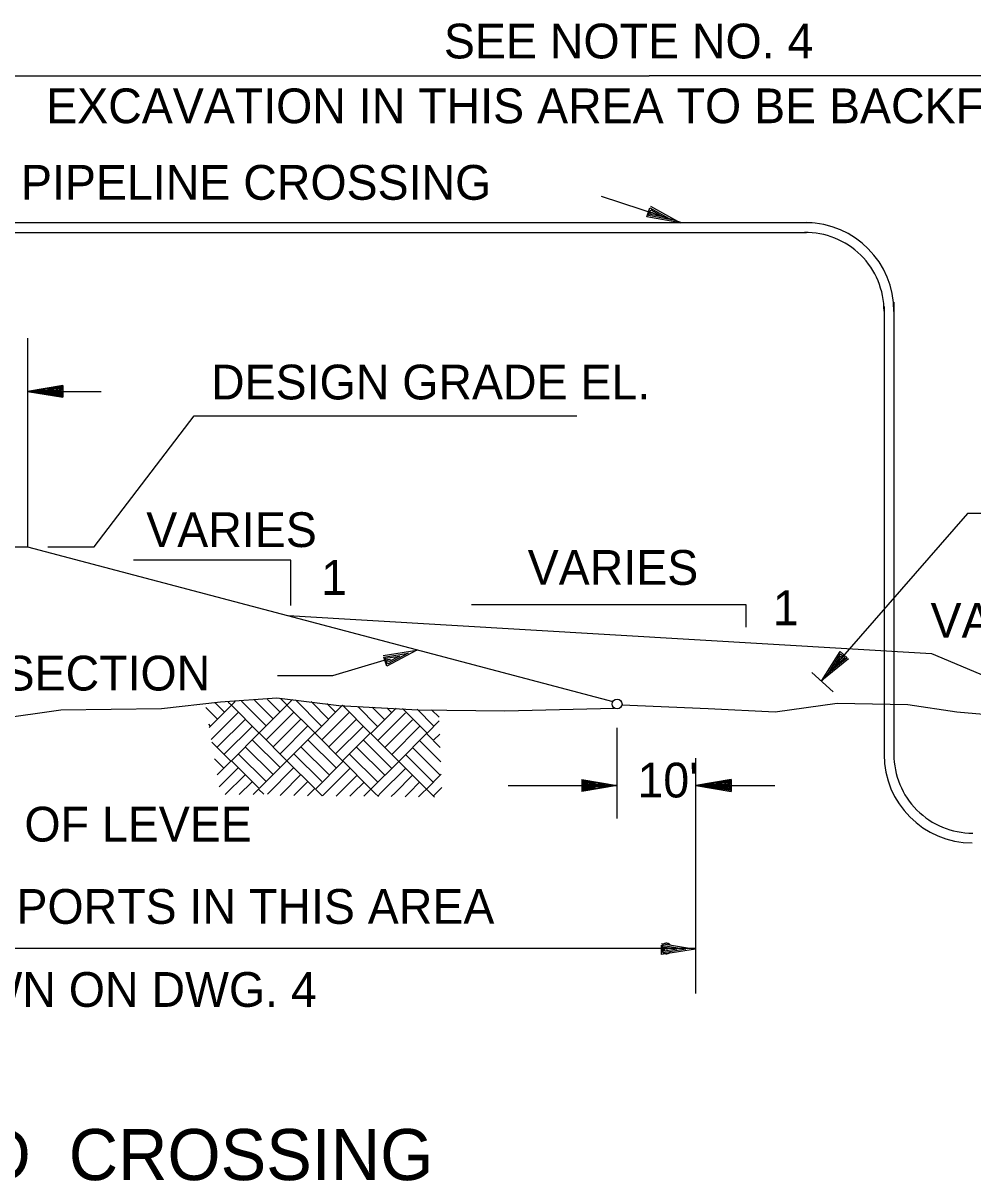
# Model space of a CAD drawing. Extents: x 2127959 to 2137375, y 2146193 to 2153470.
# Drawn here: x 2131195 to 2132094, y 2151641 to 2152738 of the extents above; entities that cross this region are included whole.
import ezdxf

# ---------------------------------------------------------------- set-up
doc = ezdxf.new("R2010")
doc.units = 0
for name, color, linetype in [('Level 1', 7, 'Continuous'), ('Level 3', 7, 'Continuous'), ('Level 5', 7, 'Continuous'), ('Level 50', 7, 'Continuous'), ('Level 63', 7, 'Continuous')]:
    doc.layers.add(name, color=color, linetype=linetype)

msp = doc.modelspace()

# ---------------------------------------------------------------- linework, layer by layer
at = {"layer": 'Level 1'}
for p, q in [((2131262.215, 2152241.498), (2131356.906, 2152365.575)), ((2132089.203, 2152273.049), (2131951.407, 2152114.92)), ((2132154.777, 2152273.049), (2132089.203, 2152273.049)), ((2131124.455, 2152241.498), (2131198.918, 2152241.498)), ((2131124.455, 2152241.498), (2131198.918, 2152241.498)), ((2131124.455, 2152241.498), (2131198.918, 2152241.498)), ((2131198.918, 2152241.498), (2131445.274, 2152176.493)), ((2131198.918, 2152241.498), (2131445.274, 2152176.493)), ((2131198.918, 2152241.498), (2131445.274, 2152176.493)), ((2131218.289, 2152241.498), (2131262.215, 2152241.498)), ((2131448.487, 2152228.906), (2131299.456, 2152228.906)), ((2131448.487, 2152185.957), (2131448.487, 2152228.906)), ((2131445.274, 2152176.493), (2131753.511, 2152095.134)), ((2131445.796, 2152176.343), (2132055.253, 2152140.601)), ((2131445.796, 2152176.343), (2132055.253, 2152140.601)), ((2131445.796, 2152176.343), (2132055.253, 2152140.601)), ((2132055.253, 2152140.601), (2132204.181, 2152077.145)), ((2132055.253, 2152140.601), (2132204.181, 2152077.145)), ((2132055.253, 2152140.601), (2132204.181, 2152077.145)), ((2131536.435, 2152133.706), (2131487.73, 2152119.307)), ((2131487.73, 2152119.307), (2131435.705, 2152119.307))]:
    msp.add_line(p, q, dxfattribs=at)
at = {"layer": 'Level 3'}
for p, q in [((2131161.687, 2152687.675), (2131787.674, 2152687.675)), ((2132413.663, 2152687.675), (2131787.674, 2152687.675)), ((2130351.811, 2152548.663), (2131942.143, 2152548.663)), ((2130351.811, 2152548.663), (2131942.143, 2152548.663)), ((2130351.811, 2152548.663), (2131942.143, 2152548.663)), ((2130352.15, 2152539.354), (2131936.796, 2152539.354)), ((2130352.15, 2152539.354), (2131936.796, 2152539.354)), ((2130352.15, 2152539.354), (2131936.796, 2152539.354)), ((2132010.232, 2152469.36), (2132010.232, 2152044.692)), ((2132010.232, 2152469.36), (2132010.232, 2152044.692)), ((2132010.232, 2152469.36), (2132010.232, 2152044.692)), ((2132019.54, 2152473.381), (2132019.54, 2152044.841)), ((2132019.54, 2152473.381), (2132019.54, 2152044.841)), ((2132019.54, 2152473.381), (2132019.54, 2152044.841)), ((2131198.918, 2152439.126), (2131198.918, 2152241.498)), ((2131232.383, 2152394.404), (2131198.918, 2152388.834)), ((2131231.698, 2152393.734), (2131204.563, 2152389.223)), ((2131231.116, 2152393.034), (2131209.955, 2152389.638)), ((2131230.312, 2152392.215), (2131217.953, 2152390.353)), ((2131229.745, 2152391.56), (2131226.202, 2152391.024)), ((2131229.687, 2152390.544), (2131229.745, 2152391.56)), ((2131230.373, 2152390.174), (2131230.312, 2152392.215)), ((2131231.163, 2152389.533), (2131231.116, 2152393.034)), ((2131231.742, 2152389.624), (2131231.698, 2152393.734)), ((2131232.383, 2152394.404), (2131232.383, 2152383.248)), ((2131198.918, 2152388.834), (2131268.706, 2152388.834)), ((2131198.918, 2152388.834), (2131268.706, 2152388.834)), ((2131198.918, 2152388.834), (2131268.706, 2152388.834)), ((2131198.918, 2152388.834), (2131232.383, 2152388.834)), ((2131198.918, 2152388.834), (2131232.383, 2152383.248)), ((2131204.563, 2152389.223), (2131231.163, 2152389.533)), ((2131231.848, 2152384.01), (2131204.653, 2152388.314)), ((2131204.653, 2152388.314), (2131231.116, 2152388.314)), ((2131209.955, 2152389.638), (2131230.373, 2152390.174)), ((2131231.191, 2152384.679), (2131210.09, 2152387.894)), ((2131210.09, 2152387.894), (2131230.444, 2152387.687)), ((2131217.953, 2152390.353), (2131229.687, 2152390.544)), ((2131230.434, 2152385.47), (2131218.116, 2152387.241)), ((2131218.116, 2152387.241), (2131229.776, 2152387.048)), ((2131229.927, 2152386.079), (2131226.188, 2152386.571)), ((2131229.776, 2152387.048), (2131229.927, 2152386.079)), ((2131230.444, 2152387.687), (2131230.434, 2152385.47)), ((2131231.116, 2152388.314), (2131231.191, 2152384.679)), ((2131231.786, 2152388.284), (2131231.848, 2152384.01)), ((2131356.906, 2152365.575), (2131719.112, 2152365.575)), ((2131619.625, 2152186.904), (2131879.397, 2152186.904)), ((2131879.397, 2152186.904), (2131879.397, 2152165.564)), ((2131941.981, 2152122.533), (2131961.923, 2152104.287)), ((2131757.396, 2151984.244), (2131757.396, 2152069.964)), ((2131757.396, 2151984.244), (2131757.396, 2152069.964)), ((2131757.396, 2151984.244), (2131757.396, 2152069.964)), ((2131831.86, 2151818.472), (2131831.86, 2152041.223)), ((2131831.86, 2151818.472), (2131831.86, 2152041.223)), ((2131831.86, 2151818.472), (2131831.86, 2152041.223)), ((2131723.916, 2152021.043), (2131723.916, 2152009.873)), ((2131723.916, 2152021.043), (2131757.396, 2152015.457)), ((2131724.573, 2152020.059), (2131724.527, 2152015.935)), ((2131725.288, 2152020.118), (2131725.272, 2152016.442)), ((2131752.437, 2152015.818), (2131725.288, 2152020.118)), ((2131746.182, 2152016.291), (2131726.019, 2152019.287)), ((2131726.019, 2152019.287), (2131726.019, 2152017.231)), ((2131736.8, 2152017.053), (2131726.808, 2152018.646)), ((2131726.808, 2152018.646), (2131726.836, 2152017.811)), ((2131865.324, 2152021.043), (2131831.86, 2152015.457)), ((2131864.64, 2152020.36), (2131837.505, 2152015.847)), ((2131864.06, 2152019.658), (2131842.897, 2152016.263)), ((2131863.254, 2152018.838), (2131850.894, 2152016.978)), ((2131863.313, 2152016.815), (2131863.254, 2152018.838)), ((2131864.105, 2152016.157), (2131864.06, 2152019.658)), ((2131864.684, 2152016.247), (2131864.64, 2152020.36)), ((2131865.324, 2152021.043), (2131865.324, 2152009.873)), ((2131654.102, 2152015.457), (2131757.396, 2152015.457)), ((2131654.102, 2152015.457), (2131757.396, 2152015.457)), ((2131654.102, 2152015.457), (2131757.396, 2152015.457)), ((2131757.396, 2152015.457), (2131723.916, 2152015.457)), ((2131757.396, 2152015.457), (2131723.916, 2152009.873)), ((2131724.396, 2152010.56), (2131752.394, 2152015.042)), ((2131724.544, 2152014.905), (2131724.396, 2152010.56)), ((2131724.527, 2152015.935), (2131752.437, 2152015.818)), ((2131752.394, 2152015.042), (2131725.229, 2152014.923)), ((2131725.229, 2152014.923), (2131725.229, 2152011.35)), ((2131725.229, 2152011.35), (2131745.988, 2152014.461)), ((2131725.272, 2152016.442), (2131746.182, 2152016.291)), ((2131745.988, 2152014.461), (2131725.929, 2152014.178)), ((2131725.929, 2152014.178), (2131726.001, 2152012.105)), ((2131726.001, 2152012.105), (2131736.949, 2152013.581)), ((2131726.019, 2152017.231), (2131736.8, 2152017.053)), ((2131736.949, 2152013.581), (2131726.778, 2152013.639)), ((2131726.778, 2152013.639), (2131726.79, 2152012.808)), ((2131726.79, 2152012.808), (2131729.89, 2152013.063)), ((2131726.836, 2152017.811), (2131730.01, 2152017.721)), ((2131831.86, 2152015.457), (2131906.682, 2152015.457)), ((2131831.86, 2152015.457), (2131865.324, 2152015.457)), ((2131831.86, 2152015.457), (2131865.324, 2152009.873)), ((2131837.505, 2152015.847), (2131864.105, 2152016.157)), ((2131864.789, 2152010.635), (2131837.595, 2152014.937)), ((2131837.595, 2152014.937), (2131864.06, 2152014.937)), ((2131842.897, 2152016.263), (2131863.313, 2152016.815)), ((2131864.134, 2152011.32), (2131843.031, 2152014.522)), ((2131843.031, 2152014.522), (2131863.387, 2152014.312)), ((2131850.894, 2152016.978), (2131862.631, 2152017.185)), ((2131863.377, 2152012.094), (2131851.059, 2152013.879)), ((2131851.059, 2152013.879), (2131862.718, 2152013.686)), ((2131862.869, 2152012.701), (2131859.129, 2152013.194)), ((2131862.687, 2152018.198), (2131859.145, 2152017.66)), ((2131862.631, 2152017.185), (2131862.687, 2152018.198)), ((2131862.718, 2152013.686), (2131862.869, 2152012.701)), ((2131863.387, 2152014.312), (2131863.377, 2152012.094)), ((2131864.06, 2152014.937), (2131864.134, 2152011.32)), ((2131864.728, 2152014.923), (2131864.789, 2152010.635)), ((2131831.86, 2151861.007), (2131143.071, 2151861.007)), ((2131831.86, 2151861.007), (2131143.071, 2151861.007)), ((2131831.86, 2151861.007), (2131143.071, 2151861.007))]:
    msp.add_line(p, q, dxfattribs=at)
msp.add_lwpolyline([(2131817.726, 2152548.663), (2131742.598, 2152573.44)], dxfattribs=at)
msp.add_circle((2131757.397, 2152092.572), 4.646, dxfattribs=at)
msp.add_circle((2131757.397, 2152092.572), 4.646, dxfattribs=at)
msp.add_circle((2131757.397, 2152092.572), 4.646, dxfattribs=at)
for centre, radius, start, end in [((2131935.764, 2152464.89), 83.775, 359.817047, 89.549108), ((2131935.764, 2152464.89), 83.775, 359.817047, 89.549108), ((2131935.764, 2152464.89), 83.775, 359.817047, 89.549108), ((2131935.755, 2152464.886), 74.476, 359.901381, 90.780836), ((2131935.755, 2152464.886), 74.476, 359.901381, 90.780836), ((2131935.755, 2152464.886), 74.476, 359.901381, 90.780836), ((2132094.001, 2152044.781), 83.771, 179.948172, 269.787253), ((2132094.001, 2152044.781), 83.771, 179.948172, 269.787253), ((2132094.001, 2152044.781), 83.771, 179.948172, 269.787253), ((2132094.001, 2152044.781), 74.463, 179.792758, 270.162028), ((2132094.001, 2152044.781), 74.463, 179.792758, 270.162028), ((2132094.001, 2152044.781), 74.463, 179.792758, 270.162028)]:
    msp.add_arc(centre, radius, start, end, dxfattribs=at)
at = {"layer": 'Level 5'}
for p, q in [((2131381.788, 2152094.731), (2131435.265, 2152098.574)), ((2131381.788, 2152094.731), (2131435.265, 2152098.574)), ((2131381.788, 2152094.731), (2131435.265, 2152098.574)), ((2131431.605, 2152078.44), (2131413.881, 2152096.161)), ((2131426.274, 2152096.965), (2131438.199, 2152085.023)), ((2131435.265, 2152098.574), (2131493.841, 2152091.129)), ((2131435.265, 2152098.574), (2131493.841, 2152091.129)), ((2131435.265, 2152098.574), (2131493.841, 2152091.129)), ((2131438.586, 2152097.769), (2131444.873, 2152091.485)), ((2131444.752, 2152091.591), (2131450.012, 2152096.845)), ((2131477.549, 2152071.722), (2131452.706, 2152096.551)), ((2131151.991, 2152075.983), (2131230.701, 2152087.046)), ((2131151.991, 2152075.983), (2131230.701, 2152087.046)), ((2131151.991, 2152075.983), (2131230.701, 2152087.046)), ((2131230.701, 2152087.046), (2131325.925, 2152088.477)), ((2131230.701, 2152087.046), (2131325.925, 2152088.477)), ((2131230.701, 2152087.046), (2131325.925, 2152088.477)), ((2131325.925, 2152088.477), (2131381.788, 2152094.731)), ((2131325.925, 2152088.477), (2131381.788, 2152094.731)), ((2131325.925, 2152088.477), (2131381.788, 2152094.731)), ((2131379.015, 2152078.32), (2131367.905, 2152089.431)), ((2131392.226, 2152091.485), (2131371.122, 2152070.397)), ((2131373.031, 2152059.123), (2131398.809, 2152084.903)), ((2131376.799, 2152093.735), (2131385.628, 2152084.903)), ((2131389.113, 2152094.539), (2131392.181, 2152091.485)), ((2131392.226, 2152091.485), (2131395.712, 2152094.974)), ((2131392.226, 2152091.485), (2131418.54, 2152065.158)), ((2131425.019, 2152071.857), (2131401.52, 2152095.357)), ((2131418.437, 2152065.26), (2131444.752, 2152091.591)), ((2131425.007, 2152058.689), (2131451.352, 2152085.052)), ((2131471.085, 2152065.26), (2131444.752, 2152091.591)), ((2131467.57, 2152094.881), (2131484.144, 2152078.32)), ((2131497.311, 2152091.471), (2131470.979, 2152065.158)), ((2131477.681, 2152058.677), (2131503.892, 2152084.888)), ((2131482.389, 2152093.231), (2131490.728, 2152084.888)), ((2131493.841, 2152091.129), (2131568.646, 2152087.046)), ((2131493.841, 2152091.129), (2131568.646, 2152087.046)), ((2131493.841, 2152091.129), (2131568.646, 2152087.046)), ((2131523.671, 2152065.158), (2131497.354, 2152091.471)), ((2131530.237, 2152071.722), (2131511.77, 2152090.191)), ((2131548.183, 2152088.613), (2131524.206, 2152064.635)), ((2131525.563, 2152089.593), (2131536.833, 2152078.32)), ((2131539.307, 2152088.998), (2131543.417, 2152084.888)), ((2131554.213, 2152088.343), (2131577.389, 2152065.168)), ((2131583.986, 2152071.738), (2131567.977, 2152087.75)), ((2131568.646, 2152087.046), (2131650.943, 2152086.319)), ((2131568.646, 2152087.046), (2131650.943, 2152086.319)), ((2131568.646, 2152087.046), (2131650.943, 2152086.319)), ((2131588.751, 2152080.122), (2131581.722, 2152087.152)), ((2131650.943, 2152086.319), (2131754.731, 2152088.76)), ((2131650.943, 2152086.319), (2131754.731, 2152088.76)), ((2131650.943, 2152086.319), (2131754.731, 2152088.76)), ((2131761.999, 2152091.917), (2131843.505, 2152088.24)), ((2131761.999, 2152091.917), (2131843.505, 2152088.24)), ((2131761.999, 2152091.917), (2131843.505, 2152088.24)), ((2131843.505, 2152088.24), (2131907.189, 2152085.365)), ((2131843.505, 2152088.24), (2131907.189, 2152085.365)), ((2131843.505, 2152088.24), (2131907.189, 2152085.365)), ((2131907.189, 2152085.365), (2131965.763, 2152093.289)), ((2131907.189, 2152085.365), (2131965.763, 2152093.289)), ((2131907.189, 2152085.365), (2131965.763, 2152093.289)), ((2131965.763, 2152093.289), (2132032.749, 2152092.082)), ((2131965.763, 2152093.289), (2132032.749, 2152092.082)), ((2131965.763, 2152093.289), (2132032.749, 2152092.082)), ((2132032.749, 2152092.082), (2132079.302, 2152085.126)), ((2132032.749, 2152092.082), (2132079.302, 2152085.126)), ((2132032.749, 2152092.082), (2132079.302, 2152085.126)), ((2132079.302, 2152085.126), (2132131.876, 2152080.794)), ((2132079.302, 2152085.126), (2132131.876, 2152080.794)), ((2132079.302, 2152085.126), (2132131.876, 2152080.794)), ((2131372.464, 2152071.722), (2131370.587, 2152073.599)), ((2131379.06, 2152051.989), (2131405.377, 2152078.32)), ((2131457.92, 2152078.426), (2131431.605, 2152052.095)), ((2131484.249, 2152052.095), (2131510.475, 2152078.32)), ((2131530.775, 2152058.021), (2131557.119, 2152084.369)), ((2131537.37, 2152051.47), (2131563.687, 2152077.798)), ((2131588.886, 2152076.623), (2131577.418, 2152065.168)), ((2131411.976, 2152071.722), (2131385.628, 2152045.378)), ((2131392.107, 2152038.946), (2131418.437, 2152065.274)), ((2131444.752, 2152038.946), (2131418.437, 2152065.26)), ((2131464.518, 2152071.873), (2131438.17, 2152045.526)), ((2131444.752, 2152038.946), (2131471.085, 2152065.26)), ((2131471.085, 2152065.26), (2131497.414, 2152038.946)), ((2131517.072, 2152071.722), (2131490.845, 2152045.498)), ((2131523.642, 2152065.158), (2131497.414, 2152038.93)), ((2131550.537, 2152038.258), (2131524.206, 2152064.59)), ((2131570.283, 2152071.202), (2131543.94, 2152044.857)), ((2131576.852, 2152064.635), (2131550.537, 2152038.305)), ((2131576.852, 2152064.59), (2131589.853, 2152051.588)), ((2131583.986, 2152058.558), (2131589.374, 2152063.95)), ((2131373.488, 2152056.4), (2131391.541, 2152038.362)), ((2131405.273, 2152052.095), (2131431.605, 2152025.779)), ((2131411.826, 2152058.689), (2131438.17, 2152032.345)), ((2131484.249, 2152025.779), (2131457.92, 2152052.095)), ((2131464.518, 2152058.689), (2131490.86, 2152032.345)), ((2131517.594, 2152058.021), (2131543.94, 2152031.677)), ((2131570.283, 2152058.021), (2131590.389, 2152037.917)), ((2131376.188, 2152040.584), (2131384.974, 2152031.797)), ((2131425.007, 2152019.18), (2131398.645, 2152045.526)), ((2131477.696, 2152019.18), (2131451.352, 2152045.526)), ((2131530.775, 2152018.496), (2131504.413, 2152044.857)), ((2131511.043, 2152051.425), (2131537.37, 2152025.094)), ((2131583.332, 2152018.63), (2131557.119, 2152044.857)), ((2131589.916, 2152025.212), (2131563.687, 2152051.425)), ((2131378.733, 2152025.553), (2131391.541, 2152038.362)), ((2131380.626, 2152014.326), (2131398.125, 2152031.809)), ((2131418.437, 2152012.612), (2131392.107, 2152038.946)), ((2131418.437, 2152012.568), (2131444.752, 2152038.901)), ((2131426.181, 2152007.193), (2131451.352, 2152032.345)), ((2131444.752, 2152038.946), (2131471.085, 2152012.612)), ((2131471.648, 2152012.048), (2131497.98, 2152038.378)), ((2131480.512, 2152007.774), (2131504.564, 2152031.827)), ((2131524.31, 2152012.048), (2131497.98, 2152038.378)), ((2131497.98, 2152038.378), (2131524.31, 2152012.048)), ((2131550.537, 2152038.258), (2131524.206, 2152011.928)), ((2131533.783, 2152008.341), (2131557.119, 2152031.677)), ((2131550.537, 2152038.258), (2131576.852, 2152011.928)), ((2131404.706, 2152025.198), (2131386.269, 2152006.761)), ((2131411.304, 2152018.646), (2131399.551, 2152006.894)), ((2131457.92, 2152025.732), (2131439.527, 2152007.327)), ((2131464.518, 2152019.18), (2131452.825, 2152007.475)), ((2131511.144, 2152025.212), (2131493.841, 2152007.909)), ((2131517.743, 2152018.661), (2131507.123, 2152008.057)), ((2131547.067, 2152008.487), (2131563.687, 2152025.094)), ((2131576.748, 2152012.048), (2131590.85, 2152026.137)), ((2131412.882, 2152007.043), (2131417.858, 2152012.031)), ((2131422.787, 2152007.147), (2131417.903, 2152012.031)), ((2131466.138, 2152007.607), (2131471.085, 2152012.568)), ((2131471.62, 2152012.048), (2131475.953, 2152007.728)), ((2131475.953, 2152007.728), (2131478.038, 2152005.63)), ((2131478.38, 2152005.63), (2131480.512, 2152007.774)), ((2131493.841, 2152007.909), (2131491.411, 2152005.479)), ((2131507.123, 2152008.057), (2131504.413, 2152005.346)), ((2131517.462, 2152005.195), (2131520.452, 2152008.206)), ((2131520.452, 2152008.206), (2131524.31, 2152012.048)), ((2131524.31, 2152012.048), (2131528.093, 2152008.28)), ((2131528.093, 2152008.28), (2131531.325, 2152005.033)), ((2131530.893, 2152005.466), (2131533.783, 2152008.341)), ((2131543.491, 2152004.899), (2131547.067, 2152008.487)), ((2131560.426, 2152008.622), (2131556.557, 2152004.751)), ((2131570.283, 2152018.496), (2131560.426, 2152008.622)), ((2131569.3, 2152004.618), (2131573.457, 2152008.771)), ((2131573.457, 2152008.771), (2131576.748, 2152012.048)), ((2131579.95, 2152008.829), (2131576.748, 2152012.048)), ((2131584.344, 2152004.437), (2131579.95, 2152008.829)), ((2131583.302, 2152005.479), (2131586.741, 2152008.905)), ((2131586.741, 2152008.905), (2131591.343, 2152013.508)), ((2131439.527, 2152007.327), (2131438.275, 2152006.075)), ((2131452.825, 2152007.475), (2131451.275, 2152005.942)), ((2131464.307, 2152005.795), (2131466.138, 2152007.607))]:
    msp.add_line(p, q, dxfattribs=at)
at = {"layer": 'Level 50'}
for p, q in [((2131808.926, 2152551.478), (2131808.926, 2152551.478)), ((2131817.305, 2152548.514), (2131817.305, 2152548.514)), ((2131559.442, 2152140.813), (2131559.442, 2152140.813)), ((2131567.865, 2152143.636), (2131567.865, 2152143.636)), ((2131957.294, 2152121.576), (2131957.294, 2152121.576)), ((2131951.407, 2152114.92), (2131951.407, 2152114.92)), ((2131822.608, 2151860.315), (2131822.608, 2151860.315)), ((2131831.493, 2151860.248), (2131831.493, 2151860.248))]:
    msp.add_line(p, q, dxfattribs=at)
for points in [[(2131788.93, 2152564.121), (2131817.305, 2152548.514), (2131785.423, 2152554.134), (2131788.426, 2152562.666), (2131808.926, 2152551.478), (2131787.287, 2152555.284), (2131789.205, 2152560.773), (2131800.876, 2152554.309), (2131789.14, 2152556.45), (2131789.924, 2152558.699), (2131792.494, 2152557.259)], [(2131535.899, 2152138.472), (2131567.865, 2152143.636), (2131539.283, 2152128.439), (2131536.396, 2152137.011), (2131559.442, 2152140.813), (2131540.041, 2152130.496), (2131538.175, 2152135.996), (2131551.35, 2152138.092), (2131540.789, 2152132.551), (2131540.025, 2152134.811), (2131542.93, 2152135.254)], [(2131976.512, 2152135.378), (2131951.407, 2152114.92), (2131968.56, 2152142.375), (2131975.346, 2152136.39), (2131957.294, 2152121.576), (2131968.939, 2152140.216), (2131973.302, 2152136.377), (2131962.936, 2152127.98), (2131969.315, 2152138.06), (2131971.11, 2152136.484), (2131968.81, 2152134.647)], [(2131799.583, 2151865.773), (2131831.493, 2151860.248), (2131799.519, 2151855.18), (2131799.582, 2151864.229), (2131822.608, 2151860.315), (2131800.903, 2151856.88), (2131800.936, 2151862.692), (2131814.074, 2151860.381), (2131802.28, 2151858.58), (2131802.291, 2151860.965), (2131805.186, 2151860.439)]]:
    msp.add_lwpolyline(points, dxfattribs=at)

# ---------------------------------------------------------------- texts
at = {"layer": 'Level 1'}
for s, p in [('SEE NOTE NO. 4', (2131593.379, 2152704.229)), ('EXCAVATION IN THIS AREA TO BE BACKFILLED', (2131216.694, 2152642.858)), ('PIPELINE CROSSING', (2131192.847, 2152570.338)), ('DESIGN GRADE EL.', (2131372.813, 2152381.184)), ('VARIES', (2131311.467, 2152241.34)), ('VARIES', (2131672.718, 2152205.549)), ('1', (2131477.19, 2152196.004)), ('1', (2131904.865, 2152167.245)), ('VARIES', (2132054.238, 2152155.441)), ('LEVEE DESIGN SECTION', (2130841.041, 2152105.442)), ("10'", (2131776.697, 2152004.096)), ('THEORETICAL TOE OF LEVEE', (2130772.775, 2151962.355)), ('NO PERMANENT PIPELINE SUPPORTS IN THIS AREA', (2130520.502, 2151884.394)), ('EXCEPT AS SHOWN ON DWG. 4', (2130797.683, 2151805.737))]:
    msp.add_text(s, height=32.931, dxfattribs=at).set_placement(p)
at = {"layer": 'Level 3'}
msp.add_text('C', height=11.17, dxfattribs=at).set_placement((2131798.352, 2151855.42))
msp.add_text('C', height=11.17, dxfattribs=at).set_placement((2131798.352, 2151855.42))
at = {"layer": 'Level 63'}
msp.add_text('ELEVATED  CROSSING', height=48.4, dxfattribs=at).set_placement((2130864.001, 2151641.589))

doc.saveas('drawing.dxf')
